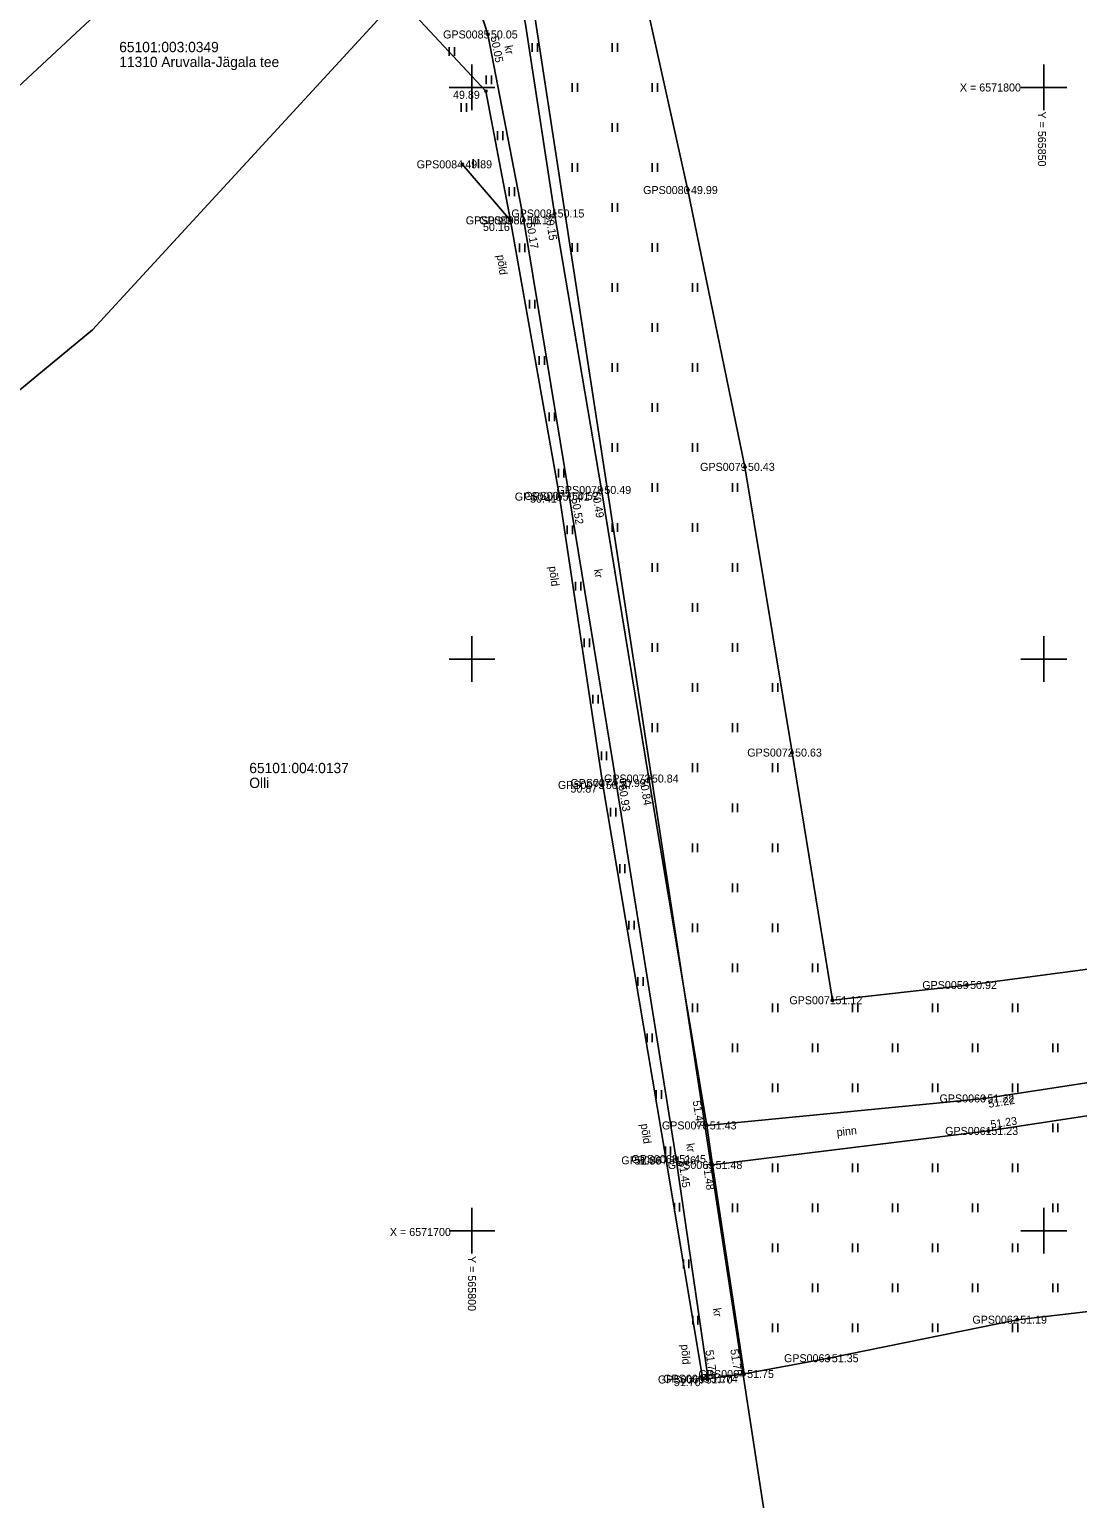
# Model space of a CAD drawing. Extents: x 563121 to 567545, y 6570841 to 6581299.
# Drawn here: x 565761.3 to 565852.9, y 6571676.6 to 6571805.1 of the extents above; entities that cross this region are included whole.
import ezdxf

# ---------------------------------------------------------------- set-up
doc = ezdxf.new("R2010")
doc.units = 0
for name, color, linetype in [('HALJASTUS', 7, 'Continuous'), ('KORGUS-EH2000', 7, 'Continuous'), ('MOOTKORG-EH2000', 7, 'Continuous'), ('MOOTMPUNKT', 7, 'Continuous'), ('MOOTNR', 7, 'Continuous'), ('MOOTPIIR', 7, 'Continuous'), ('PIIR', 7, 'Continuous'), ('TEE', 7, 'Continuous'), ('VORK', 7, 'Continuous')]:
    doc.layers.add(name, color=color, linetype=linetype)

msp = doc.modelspace()

# ---------------------------------------------------------------- linework, layer by layer
at = {"layer": 'HALJASTUS'}
for p, q in [((565798.01, 6571803.51), (565798.01, 6571802.75)), ((565798.47, 6571803.51), (565798.47, 6571802.75)), ((565805.27, 6571803.88), (565805.27, 6571803.12)), ((565805.73, 6571803.88), (565805.73, 6571803.12)), ((565812.27, 6571803.88), (565812.27, 6571803.12)), ((565812.73, 6571803.88), (565812.73, 6571803.12)), ((565801.25, 6571801.05), (565801.25, 6571800.29)), ((565801.7, 6571801.05), (565801.7, 6571800.29)), ((565808.77, 6571800.38), (565808.77, 6571799.62)), ((565809.23, 6571800.38), (565809.23, 6571799.62)), ((565815.77, 6571800.38), (565815.77, 6571799.62)), ((565816.23, 6571800.38), (565816.23, 6571799.62)), ((565799.07, 6571798.62), (565799.07, 6571797.86)), ((565799.52, 6571798.62), (565799.52, 6571797.86)), ((565812.27, 6571796.88), (565812.27, 6571796.12)), ((565812.73, 6571796.88), (565812.73, 6571796.12)), ((565802.25, 6571796.16), (565802.25, 6571795.39)), ((565802.71, 6571796.16), (565802.71, 6571795.39)), ((565800.12, 6571793.73), (565800.12, 6571792.97)), ((565800.57, 6571793.73), (565800.57, 6571792.97)), ((565808.77, 6571793.38), (565808.77, 6571792.62)), ((565809.23, 6571793.38), (565809.23, 6571792.62)), ((565815.77, 6571793.38), (565815.77, 6571792.62)), ((565816.23, 6571793.38), (565816.23, 6571792.62)), ((565803.26, 6571791.26), (565803.26, 6571790.5)), ((565803.72, 6571791.26), (565803.72, 6571790.5)), ((565812.27, 6571789.88), (565812.27, 6571789.12)), ((565812.73, 6571789.88), (565812.73, 6571789.12)), ((565804.17, 6571786.34), (565804.17, 6571785.58)), ((565804.63, 6571786.34), (565804.63, 6571785.58)), ((565808.77, 6571786.38), (565808.77, 6571785.62)), ((565809.23, 6571786.38), (565809.23, 6571785.62)), ((565815.77, 6571786.38), (565815.77, 6571785.62)), ((565816.23, 6571786.38), (565816.23, 6571785.62)), ((565812.27, 6571782.88), (565812.27, 6571782.12)), ((565812.73, 6571782.88), (565812.73, 6571782.12)), ((565819.27, 6571782.88), (565819.27, 6571782.12)), ((565819.73, 6571782.88), (565819.73, 6571782.12)), ((565805.03, 6571781.42), (565805.03, 6571780.66)), ((565805.49, 6571781.42), (565805.49, 6571780.66)), ((565815.77, 6571779.38), (565815.77, 6571778.62)), ((565816.23, 6571779.38), (565816.23, 6571778.62)), ((565805.89, 6571776.49), (565805.89, 6571775.73)), ((565806.35, 6571776.49), (565806.35, 6571775.73)), ((565812.27, 6571775.88), (565812.27, 6571775.12)), ((565812.73, 6571775.88), (565812.73, 6571775.12)), ((565819.27, 6571775.88), (565819.27, 6571775.12)), ((565819.73, 6571775.88), (565819.73, 6571775.12)), ((565815.77, 6571772.38), (565815.77, 6571771.62)), ((565816.23, 6571772.38), (565816.23, 6571771.62)), ((565806.75, 6571771.57), (565806.75, 6571770.8)), ((565807.21, 6571771.57), (565807.21, 6571770.8)), ((565812.27, 6571768.88), (565812.27, 6571768.12)), ((565812.73, 6571768.88), (565812.73, 6571768.12)), ((565819.27, 6571768.88), (565819.27, 6571768.12)), ((565819.73, 6571768.88), (565819.73, 6571768.12)), ((565807.58, 6571766.63), (565807.58, 6571765.87)), ((565808.03, 6571766.63), (565808.03, 6571765.87)), ((565815.77, 6571765.38), (565815.77, 6571764.62)), ((565816.23, 6571765.38), (565816.23, 6571764.62)), ((565822.77, 6571765.38), (565822.77, 6571764.62)), ((565823.23, 6571765.38), (565823.23, 6571764.62)), ((565812.27, 6571761.88), (565812.27, 6571761.12)), ((565812.73, 6571761.88), (565812.73, 6571761.12)), ((565819.27, 6571761.88), (565819.27, 6571761.12)), ((565819.73, 6571761.88), (565819.73, 6571761.12)), ((565808.33, 6571761.69), (565808.33, 6571760.93)), ((565808.78, 6571761.69), (565808.78, 6571760.93)), ((565815.77, 6571758.38), (565815.77, 6571757.62)), ((565816.23, 6571758.38), (565816.23, 6571757.62)), ((565822.77, 6571758.38), (565822.77, 6571757.62)), ((565823.23, 6571758.38), (565823.23, 6571757.62)), ((565809.07, 6571756.75), (565809.07, 6571755.99)), ((565809.53, 6571756.75), (565809.53, 6571755.99)), ((565819.27, 6571754.88), (565819.27, 6571754.12)), ((565819.73, 6571754.88), (565819.73, 6571754.12)), ((565809.82, 6571751.8), (565809.82, 6571751.04)), ((565810.28, 6571751.8), (565810.28, 6571751.04)), ((565815.77, 6571751.38), (565815.77, 6571750.62)), ((565816.23, 6571751.38), (565816.23, 6571750.62)), ((565822.77, 6571751.38), (565822.77, 6571750.62)), ((565823.23, 6571751.38), (565823.23, 6571750.62)), ((565819.27, 6571747.88), (565819.27, 6571747.12)), ((565819.73, 6571747.88), (565819.73, 6571747.12)), ((565826.27, 6571747.88), (565826.27, 6571747.12)), ((565826.73, 6571747.88), (565826.73, 6571747.12)), ((565810.57, 6571746.86), (565810.57, 6571746.1)), ((565811.03, 6571746.86), (565811.03, 6571746.1)), ((565815.77, 6571744.38), (565815.77, 6571743.62)), ((565816.23, 6571744.38), (565816.23, 6571743.62)), ((565822.77, 6571744.38), (565822.77, 6571743.62)), ((565823.23, 6571744.38), (565823.23, 6571743.62)), ((565811.33, 6571741.92), (565811.33, 6571741.16)), ((565811.78, 6571741.92), (565811.78, 6571741.16)), ((565819.27, 6571740.88), (565819.27, 6571740.12)), ((565819.73, 6571740.88), (565819.73, 6571740.12)), ((565826.27, 6571740.88), (565826.27, 6571740.12)), ((565826.73, 6571740.88), (565826.73, 6571740.12)), ((565822.77, 6571737.38), (565822.77, 6571736.62)), ((565823.23, 6571737.38), (565823.23, 6571736.62)), ((565812.12, 6571736.98), (565812.12, 6571736.22)), ((565812.58, 6571736.98), (565812.58, 6571736.22)), ((565819.27, 6571733.88), (565819.27, 6571733.12)), ((565819.73, 6571733.88), (565819.73, 6571733.12)), ((565826.27, 6571733.88), (565826.27, 6571733.12)), ((565826.73, 6571733.88), (565826.73, 6571733.12)), ((565812.92, 6571732.05), (565812.92, 6571731.28)), ((565813.38, 6571732.05), (565813.38, 6571731.28)), ((565822.77, 6571730.38), (565822.77, 6571729.62)), ((565823.23, 6571730.38), (565823.23, 6571729.62)), ((565813.72, 6571727.11), (565813.72, 6571726.35)), ((565814.17, 6571727.11), (565814.17, 6571726.35)), ((565819.27, 6571726.88), (565819.27, 6571726.12)), ((565819.73, 6571726.88), (565819.73, 6571726.12)), ((565826.27, 6571726.88), (565826.27, 6571726.12)), ((565826.73, 6571726.88), (565826.73, 6571726.12)), ((565822.77, 6571723.38), (565822.77, 6571722.62)), ((565823.23, 6571723.38), (565823.23, 6571722.62)), ((565829.77, 6571723.38), (565829.77, 6571722.62)), ((565830.23, 6571723.38), (565830.23, 6571722.62)), ((565814.51, 6571722.17), (565814.51, 6571721.41)), ((565814.97, 6571722.17), (565814.97, 6571721.41)), ((565819.27, 6571719.88), (565819.27, 6571719.12)), ((565819.73, 6571719.88), (565819.73, 6571719.12)), ((565826.27, 6571719.88), (565826.27, 6571719.12)), ((565826.73, 6571719.88), (565826.73, 6571719.12)), ((565833.27, 6571719.88), (565833.27, 6571719.12)), ((565833.73, 6571719.88), (565833.73, 6571719.12)), ((565840.27, 6571719.88), (565840.27, 6571719.12)), ((565840.73, 6571719.88), (565840.73, 6571719.12)), ((565847.27, 6571719.88), (565847.27, 6571719.12)), ((565847.73, 6571719.88), (565847.73, 6571719.12)), ((565815.31, 6571717.24), (565815.31, 6571716.48)), ((565815.77, 6571717.24), (565815.77, 6571716.48)), ((565822.77, 6571716.38), (565822.77, 6571715.62)), ((565823.23, 6571716.38), (565823.23, 6571715.62)), ((565829.77, 6571716.38), (565829.77, 6571715.62)), ((565830.23, 6571716.38), (565830.23, 6571715.62)), ((565836.77, 6571716.38), (565836.77, 6571715.62)), ((565837.23, 6571716.38), (565837.23, 6571715.62)), ((565843.77, 6571716.38), (565843.77, 6571715.62)), ((565844.23, 6571716.38), (565844.23, 6571715.62)), ((565850.77, 6571716.38), (565850.77, 6571715.62)), ((565851.23, 6571716.38), (565851.23, 6571715.62)), ((565816.11, 6571712.3), (565816.11, 6571711.54)), ((565816.56, 6571712.3), (565816.56, 6571711.54)), ((565826.27, 6571712.88), (565826.27, 6571712.12)), ((565826.73, 6571712.88), (565826.73, 6571712.12)), ((565833.27, 6571712.88), (565833.27, 6571712.12)), ((565833.73, 6571712.88), (565833.73, 6571712.12)), ((565840.27, 6571712.88), (565840.27, 6571712.12)), ((565840.73, 6571712.88), (565840.73, 6571712.12)), ((565847.27, 6571712.88), (565847.27, 6571712.12)), ((565847.73, 6571712.88), (565847.73, 6571712.12)), ((565850.77, 6571709.38), (565850.77, 6571708.62)), ((565851.23, 6571709.38), (565851.23, 6571708.62)), ((565816.91, 6571707.36), (565816.91, 6571706.6)), ((565817.36, 6571707.36), (565817.36, 6571706.6)), ((565826.27, 6571705.88), (565826.27, 6571705.12)), ((565826.73, 6571705.88), (565826.73, 6571705.12)), ((565833.27, 6571705.88), (565833.27, 6571705.12)), ((565833.73, 6571705.88), (565833.73, 6571705.12)), ((565840.27, 6571705.88), (565840.27, 6571705.12)), ((565840.73, 6571705.88), (565840.73, 6571705.12)), ((565847.27, 6571705.88), (565847.27, 6571705.12)), ((565847.73, 6571705.88), (565847.73, 6571705.12)), ((565817.7, 6571702.43), (565817.7, 6571701.67)), ((565818.16, 6571702.43), (565818.16, 6571701.67)), ((565822.77, 6571702.38), (565822.77, 6571701.62)), ((565823.23, 6571702.38), (565823.23, 6571701.62)), ((565829.77, 6571702.38), (565829.77, 6571701.62)), ((565830.23, 6571702.38), (565830.23, 6571701.62)), ((565836.77, 6571702.38), (565836.77, 6571701.62)), ((565837.23, 6571702.38), (565837.23, 6571701.62)), ((565843.77, 6571702.38), (565843.77, 6571701.62)), ((565844.23, 6571702.38), (565844.23, 6571701.62)), ((565850.77, 6571702.38), (565850.77, 6571701.62)), ((565851.23, 6571702.38), (565851.23, 6571701.62)), ((565826.27, 6571698.88), (565826.27, 6571698.12)), ((565826.73, 6571698.88), (565826.73, 6571698.12)), ((565833.27, 6571698.88), (565833.27, 6571698.12)), ((565833.73, 6571698.88), (565833.73, 6571698.12)), ((565840.27, 6571698.88), (565840.27, 6571698.12)), ((565840.73, 6571698.88), (565840.73, 6571698.12)), ((565847.27, 6571698.88), (565847.27, 6571698.12)), ((565847.73, 6571698.88), (565847.73, 6571698.12)), ((565818.5, 6571697.49), (565818.5, 6571696.73)), ((565818.95, 6571697.49), (565818.95, 6571696.73)), ((565829.77, 6571695.38), (565829.77, 6571694.62)), ((565830.23, 6571695.38), (565830.23, 6571694.62)), ((565836.77, 6571695.38), (565836.77, 6571694.62)), ((565837.23, 6571695.38), (565837.23, 6571694.62)), ((565843.77, 6571695.38), (565843.77, 6571694.62)), ((565844.23, 6571695.38), (565844.23, 6571694.62)), ((565850.77, 6571695.38), (565850.77, 6571694.62)), ((565851.23, 6571695.38), (565851.23, 6571694.62)), ((565819.3, 6571692.56), (565819.3, 6571691.8)), ((565819.75, 6571692.56), (565819.75, 6571691.8)), ((565826.27, 6571691.88), (565826.27, 6571691.12)), ((565826.73, 6571691.88), (565826.73, 6571691.12)), ((565833.27, 6571691.88), (565833.27, 6571691.12)), ((565833.73, 6571691.88), (565833.73, 6571691.12)), ((565840.27, 6571691.88), (565840.27, 6571691.12)), ((565840.73, 6571691.88), (565840.73, 6571691.12)), ((565847.27, 6571691.88), (565847.27, 6571691.12)), ((565847.73, 6571691.88), (565847.73, 6571691.12)), ((565820.09, 6571687.62), (565820.09, 6571686.86)), ((565820.55, 6571687.62), (565820.55, 6571686.86))]:
    msp.add_line(p, q, dxfattribs=at)
msp.add_lwpolyline([(565799.16, 6571793.27), (565803.38, 6571788.37), (565807.67, 6571764.21), (565811.44, 6571738.99), (565816.98, 6571706.16), (565820.18, 6571686.99)], dxfattribs=at)
at = {"layer": 'KORGUS-EH2000'}
for centre in [(565801.4, 6571804.63), (565801.22, 6571799.67), (565799.16, 6571793.27), (565818.89, 6571791.02), (565807.23, 6571788.97), (565803.38, 6571788.37), (565804.55, 6571788.37), (565823.87, 6571766.81), (565807.67, 6571764.21), (565808.49, 6571764.27), (565811.32, 6571764.79), (565827.99, 6571741.82), (565811.44, 6571738.99), (565812.6, 6571739.16), (565815.47, 6571739.55), (565843.29, 6571721.49), (565831.52, 6571720.16), (565844.8, 6571711.57), (565820.53, 6571709.21), (565845.15, 6571708.73), (565816.98, 6571706.16), (565817.86, 6571706.27), (565821.04, 6571705.75), (565847.67, 6571692.22), (565831.2, 6571688.85), (565823.8, 6571687.47), (565820.18, 6571686.99), (565820.64, 6571687.06)]:
    msp.add_circle(centre, 0.1, dxfattribs=at)
at = {"layer": 'MOOTMPUNKT'}
for centre in [(565801.4, 6571804.63), (565799.16, 6571793.27), (565818.89, 6571791.02), (565807.23, 6571788.97), (565803.38, 6571788.37), (565804.55, 6571788.37), (565823.87, 6571766.81), (565807.67, 6571764.21), (565808.49, 6571764.27), (565811.32, 6571764.79), (565827.99, 6571741.82), (565811.44, 6571738.99), (565812.6, 6571739.16), (565815.47, 6571739.55), (565843.29, 6571721.49), (565831.52, 6571720.16), (565844.8, 6571711.57), (565820.53, 6571709.21), (565845.15, 6571708.73), (565816.98, 6571706.16), (565817.86, 6571706.27), (565821.04, 6571705.75), (565847.67, 6571692.22), (565831.2, 6571688.85), (565823.8, 6571687.47), (565820.18, 6571686.99), (565820.64, 6571687.06)]:
    msp.add_circle(centre, 0.1, dxfattribs=at)
at = {"layer": 'MOOTPIIR'}
for points in [[(565867.26, 6571724.67), (565843.29, 6571721.49), (565831.52, 6571720.16), (565827.99, 6571741.82), (565823.87, 6571766.81), (565818.89, 6571791.02), (565813.7, 6571814.39)], [(565790.17, 6571811.53), (565801.22, 6571799.67), (565803.38, 6571788.37), (565807.67, 6571764.21), (565811.44, 6571738.99), (565816.98, 6571706.16), (565820.18, 6571686.99), (565820.64, 6571687.06), (565823.8, 6571687.47), (565831.2, 6571688.85), (565847.67, 6571692.22), (565872.55, 6571695.12)]]:
    msp.add_lwpolyline(points, dxfattribs=at)
at = {"layer": 'PIIR'}
for points in [[(566138.88, 6572289.1), (566071.95, 6572189.53), (566056.92, 6572168.48), (566043.44, 6572149.59), (566020.47, 6572117.41), (565845.87, 6571876.56), (565833.02, 6571860.66), (565803.59, 6571818.77), (565766.84, 6571778.8), (565712.27, 6571733.72), (565636.36, 6571689.97), (565561.65, 6571658.97), (565400, 6571600), (565315, 6571572), (565230, 6571552), (564980, 6571552), (564921.56, 6571543.26)], [(564959.63, 6571567.88), (565247.22, 6571575.87), (565310, 6571592), (565385.09, 6571617.94), (565603.34, 6571696.36), (565663.71, 6571724.88), (565720.01, 6571762.52), (565767.05, 6571806.3), (565831.51, 6571891.07), (565894.85, 6571978.6), (565929.68, 6572026.82), (566028.25, 6572163.26), (566043.71, 6572184.75), (566068.58, 6572219.3), (566114.67, 6572283.35)]]:
    msp.add_lwpolyline(points, dxfattribs=at)
for points in [[(565385.09, 6571617.94), (565348.3, 6571706.93), (565808.88, 6572174.3), (565817.95, 6572187.54), (565914.67, 6572223.63), (565927.34, 6572201.79), (566013.66, 6572213.36), (566028.25, 6572163.26), (565929.68, 6572026.82), (565869.35, 6572071.5), (565833.75, 6572019.48), (565773.79, 6571931.89), (565831.51, 6571891.07), (565767.05, 6571806.3), (565720.01, 6571762.52), (565663.71, 6571724.88), (565603.34, 6571696.36)], [(565833.02, 6571860.66), (565851.06, 6571859.65), (565901.01, 6571846.54), (565960.44, 6571833.78), (565973.49, 6571828.72), (566023.53, 6571796.39), (566089.86, 6571753.57), (566110.96, 6571742.32), (566147.53, 6571725.81), (566160.83, 6571717.7), (565835.49, 6571610.61), (565803.59, 6571818.77)], [(565803.59, 6571818.77), (565835.49, 6571610.61), (565859.22, 6571454.59), (565609.76, 6571322.76), (565540, 6571330), (565490, 6571465), (565440, 6571540), (565400, 6571600), (565561.65, 6571658.97), (565636.36, 6571689.97), (565712.27, 6571733.72), (565766.84, 6571778.8)]]:
    msp.add_lwpolyline(points, close=True, dxfattribs=at)
at = {"layer": 'TEE'}
for points in [[(565833.44, 6571863.77), (565828.71, 6571861.71), (565827.37, 6571860.22), (565817.96, 6571847.83), (565804.53, 6571830.72), (565801.58, 6571826.8), (565800.95, 6571825.15), (565801.03, 6571821.87), (565801.47, 6571818.98), (565802.63, 6571814.64), (565802.72, 6571813.36), (565804.67, 6571805.69), (565807.23, 6571788.97), (565811.32, 6571764.79), (565815.47, 6571739.55), (565820.53, 6571709.21), (565821.04, 6571705.75), (565823.8, 6571687.47)], [(565790.17, 6571811.53), (565793.42, 6571812.59), (565796.72, 6571811.56), (565799.53, 6571810.47), (565801.4, 6571804.63), (565804.55, 6571788.37), (565808.49, 6571764.27), (565812.6, 6571739.16), (565817.86, 6571706.27), (565820.64, 6571687.06)], [(565820.53, 6571709.21), (565844.8, 6571711.57), (565868.94, 6571715.28), (565894.17, 6571719.34)], [(565821.04, 6571705.75), (565845.15, 6571708.73), (565869.25, 6571712.41), (565894.5, 6571716.3)]]:
    msp.add_lwpolyline(points, dxfattribs=at)
at = {"layer": 'VORK'}
for p, q in [((565800, 6571802), (565800, 6571798)), ((565850, 6571802), (565850, 6571798)), ((565798, 6571800), (565802, 6571800)), ((565848, 6571800), (565852, 6571800)), ((565800, 6571752), (565800, 6571748)), ((565850, 6571752), (565850, 6571748)), ((565798, 6571750), (565802, 6571750)), ((565848, 6571750), (565852, 6571750)), ((565800, 6571702), (565800, 6571698)), ((565850, 6571702), (565850, 6571698)), ((565798, 6571700), (565802, 6571700)), ((565848, 6571700), (565852, 6571700))]:
    msp.add_line(p, q, dxfattribs=at)

# ---------------------------------------------------------------- texts
at = {"layer": 'HALJASTUS'}
for rotation, p in [(278.0449, (565802.18, 6571785.31)), (277.0425, (565806.73, 6571758.08)), (278.0449, (565814.75, 6571709.32)), (274.4106, (565818.28, 6571690.04))]:
    msp.add_text('põld', height=0.7, rotation=rotation, dxfattribs=at).set_placement(p)
at = {"layer": 'KORGUS-EH2000'}
for s, rotation, p in [(' 50.05', 280.9361, (565801.58, 6571804.67)), (' 50.15', 278.7015, (565806.37, 6571789.14)), (' 50.17', 279.2902, (565804.72, 6571788.4)), (' 50.49', 279.5852, (565810.45, 6571764.86)), (' 50.52', 279.3018, (565808.66, 6571764.29)), (' 50.93', 279.0806, (565812.77, 6571739.19)), (' 50.84', 279.3564, (565814.62, 6571739.72)), (' 51.22', 8.7443, (565844.93, 6571710.71)), (' 51.43', 279.4603, (565819.25, 6571711.59)), (' 51.23', 8.6755, (565845.13, 6571708.9)), (' 51.45', 278.2325, (565818.03, 6571706.3)), (' 51.48', 278.3657, (565820.15, 6571706.09)), (' 51.74', 278.2325, (565820.37, 6571689.78)), (' 51.75', 278.5978, (565822.55, 6571689.86))]:
    msp.add_text(s, height=0.7, rotation=rotation, dxfattribs=at).set_placement(p)
for s, p in [(' 49.89', (565798.09, 6571799)), (' 49.89', (565799.16, 6571792.92)), (' 49.99', (565818.89, 6571790.67)), (' 50.16', (565800.71, 6571787.44)), (' 50.43', (565823.87, 6571766.46)), (' 50.41', (565804.83, 6571763.68)), (' 50.63', (565827.99, 6571741.47)), (' 50.87', (565808.35, 6571738.32)), (' 50.92', (565843.29, 6571721.14)), (' 51.12', (565831.52, 6571719.81)), (' 51.36', (565813.95, 6571705.79)), (' 51.19', (565847.67, 6571691.87)), (' 51.35', (565831.2, 6571688.5)), (' 51.70', (565817.39, 6571686.41))]:
    msp.add_text(s, height=0.7, dxfattribs=at).set_placement(p)
at = {"layer": 'MOOTKORG-EH2000'}
for s, p in [(' 50.05', (565801.4, 6571804.28)), (' 49.89', (565799.16, 6571792.92)), (' 49.99', (565818.89, 6571790.67)), (' 50.16', (565803.38, 6571788.02)), (' 50.17', (565804.55, 6571788.02)), (' 50.15', (565807.23, 6571788.62)), (' 50.43', (565823.87, 6571766.46)), (' 50.41', (565807.67, 6571763.86)), (' 50.52', (565808.49, 6571763.92)), (' 50.49', (565811.32, 6571764.44)), (' 50.63', (565827.99, 6571741.47)), (' 50.84', (565815.47, 6571739.2)), (' 50.87', (565811.44, 6571738.64)), (' 50.93', (565812.6, 6571738.81)), (' 50.92', (565843.29, 6571721.14)), (' 51.12', (565831.52, 6571719.81)), (' 51.22', (565844.8, 6571711.22)), (' 51.43', (565820.53, 6571708.86)), (' 51.23', (565845.15, 6571708.38)), (' 51.36', (565816.98, 6571705.81)), (' 51.45', (565817.86, 6571705.92)), (' 51.48', (565821.04, 6571705.4)), (' 51.19', (565847.67, 6571691.87)), (' 51.35', (565831.2, 6571688.5)), (' 51.70', (565820.18, 6571686.64)), (' 51.74', (565820.64, 6571686.71)), (' 51.75', (565823.8, 6571687.12))]:
    msp.add_text(s, height=0.7, dxfattribs=at).set_placement(p)
at = {"layer": 'MOOTNR'}
for s, p in [('GPS0085 ', (565797.48, 6571804.28)), ('GPS0084 ', (565795.17, 6571792.92)), ('GPS0080 ', (565814.97, 6571790.67)), ('GPS0083 ', (565799.46, 6571788.02)), ('GPS0082 ', (565800.63, 6571788.02)), ('GPS0081 ', (565803.45, 6571788.62)), ('GPS0079 ', (565819.95, 6571766.46)), ('GPS0076 ', (565803.75, 6571763.86)), ('GPS0077 ', (565804.57, 6571763.92)), ('GPS0078 ', (565807.4, 6571764.44)), ('GPS0072 ', (565824.07, 6571741.47)), ('GPS0073 ', (565811.55, 6571739.2)), ('GPS0075 ', (565807.52, 6571738.64)), ('GPS0074 ', (565808.61, 6571738.81)), ('GPS0059 ', (565839.37, 6571721.14)), ('GPS0071 ', (565827.75, 6571719.81)), ('GPS0060 ', (565840.88, 6571711.22)), ('GPS0070 ', (565816.61, 6571708.86)), ('GPS0061 ', (565841.37, 6571708.38)), ('GPS0067 ', (565813.06, 6571705.81)), ('GPS0068 ', (565813.94, 6571705.92)), ('GPS0069 ', (565817.12, 6571705.4)), ('GPS0062 ', (565843.75, 6571691.87)), ('GPS0063 ', (565827.28, 6571688.5)), ('GPS0066 ', (565816.26, 6571686.64)), ('GPS0065 ', (565816.72, 6571686.71)), ('GPS0064 ', (565819.81, 6571687.12))]:
    msp.add_text(s, height=0.7, dxfattribs=at).set_placement(p)
at = {"layer": 'PIIR'}
for s, p in [('65101:003:0349', (565769.17, 6571803.08)), ('11310 Aruvalla-Jägala tee', (565769.17, 6571801.78)), ('65101:004:0137', (565780.54, 6571740.02)), ('Olli', (565780.54, 6571738.72))]:
    msp.add_text(s, height=0.9, dxfattribs=at).set_placement(p)
at = {"layer": 'TEE'}
for s, rotation, p in [('kr', 280.8333, (565802.85, 6571803.61)), ('kr', 278.7531, (565810.67, 6571757.82)), ('pinn', 6.1546, (565831.92, 6571708.26)), ('kr', 279.3233, (565818.72, 6571707.59)), ('kr', 278.6952, (565821.06, 6571693.19))]:
    msp.add_text(s, height=0.7, rotation=rotation, dxfattribs=at).set_placement(p)
at = {"layer": 'VORK'}
for s, p in [('X = 6571800', (565842.66, 6571799.64)), ('X = 6571700', (565792.83, 6571699.54))]:
    msp.add_text(s, height=0.7, dxfattribs=at).set_placement(p)
for s, p in [('Y = 565850 ', (565849.48, 6571797.89)), ('Y = 565800 ', (565799.65, 6571697.79))]:
    msp.add_text(s, height=0.7, rotation=270, dxfattribs=at).set_placement(p)

doc.saveas('drawing.dxf')
